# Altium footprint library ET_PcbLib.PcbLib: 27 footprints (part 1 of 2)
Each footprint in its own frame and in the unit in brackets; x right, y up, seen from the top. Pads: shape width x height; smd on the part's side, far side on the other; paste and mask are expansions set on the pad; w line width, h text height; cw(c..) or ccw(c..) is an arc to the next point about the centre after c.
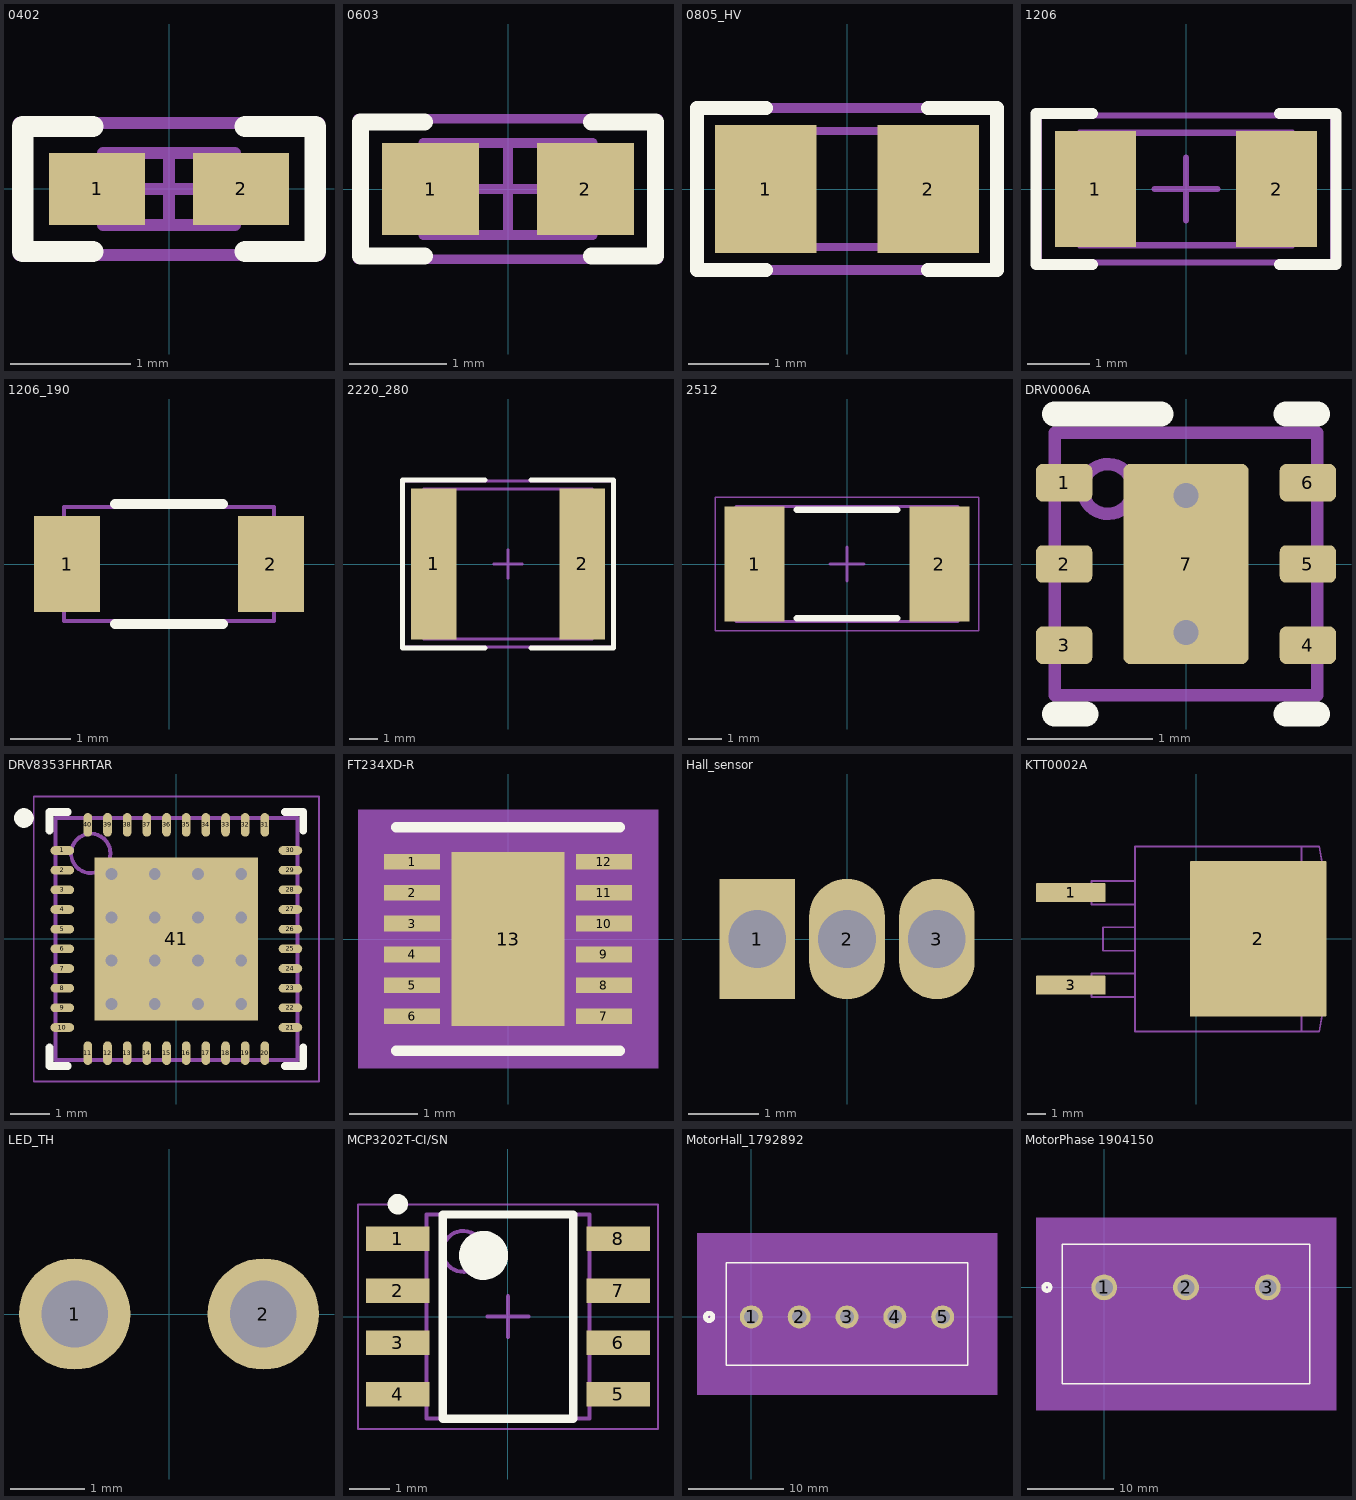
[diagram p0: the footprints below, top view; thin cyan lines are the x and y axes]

## 0402 [mm] "0402 from SM-752 data"
height 0.6
pads (2):
  rect 0.8x0.6 smd: 1(-0.6,0) 2(0.6,0)
Top Overlay:
  lines w0.178: -0.635,-0.521 -1.219,-0.521 -1.219,0.521 -0.635,0.521 ; 0.635,-0.521 1.219,-0.521 1.219,0.521 0.635,0.521
Mechanical 5:
  lines w0.1: -1.25,-0.55 1.25,-0.55 1.25,0.55 -1.25,0.55 -1.25,-0.55
  text ".Designator" at -1.117,-0.305 h0.61
Mechanical 13:
  lines w0.1: -0.35,-0.3 -0.35,0.3 ; 0.35,-0.3 0.35,0.3 ; -0.55,-0.3 -0.55,0.3 0.55,0.3 0.55,-0.3 -0.55,-0.3
Mechanical 15:
  lines w0.1: -0.3,0 0.3,0 ; 0,-0.3 0,0.3 ; -1.25,-0.55 -1.25,0.55 1.25,0.55 1.25,-0.55 -1.25,-0.55
3D body: height 0.6, standoff 0, extent -0.549,-0.299 -0.351,0.299
3D body: height 0.6, standoff 0, extent -0.349,-0.299 0.349,0.299
3D body: height 0.6, standoff 0, extent 0.351,-0.299 0.549,0.299

## 0603 [mm] "0603 from SM-752 data"
height 1
pads (2):
  rect 1x0.95 smd: 1(-0.8,0) 2(0.8,0)
Top Overlay:
  lines w0.178: -0.864,-0.691 -1.524,-0.691 -1.524,0.693 -0.864,0.693 ; 0.864,-0.691 1.524,-0.691 1.524,0.693 0.864,0.693
Mechanical 5:
  lines w0.1: -1.55,-0.725 -1.55,0.725 1.55,0.725 1.55,-0.725 -1.55,-0.725
  text ".Designator" at -1.397,-0.381 h0.76
Mechanical 13:
  lines w0.1: -0.55,-0.475 -0.55,0.475 ; 0.55,-0.475 0.55,0.475 ; -0.875,-0.475 0.875,-0.475 0.875,0.475 -0.875,0.475 -0.875,-0.475
Mechanical 15:
  lines w0.1: -0.475,0 0.475,0 ; 0,-0.475 0,0.475 ; -1.55,-0.725 1.55,-0.725 1.55,0.725 -1.55,0.725 -1.55,-0.725
3D body: height 1, standoff 0, extent -0.874,-0.474 -0.551,0.474
3D body: height 1, standoff 0, extent -0.549,-0.474 0.549,0.474
3D body: height 1, standoff 0, extent 0.551,-0.474 0.874,0.474

## 0805_HV [mil] "0805 with 30mil clearance between pads"
height 57.09
pads (2):
  rect 50x63 smd: 1(-40,0) 2(40,0)
Top Overlay:
  lines w7: -40,-40 -74,-40 -74,0 -74,40 -40,40 ; 40,-40 74,-40 74,0 74,40 40,40
Mechanical 5:
  lines w5: -74,-40 -74,40 74,40 74,-40 -74,-40
  text ".Designator" at -64,-17 h35
Mechanical 13:
  lines w3.94: -25.59,-28.54 -25.59,28.54 ; 25.59,-28.54 25.59,28.54 ; -43.31,-28.54 -43.31,28.54 43.31,28.54 43.31,-28.54 -43.31,-28.54
3D body: height 57.09, standoff 0, extent 25.61,-28.52 43.29,28.52
3D body: height 57.09, standoff 0, extent -25.57,-28.52 25.57,28.52
3D body: height 57.09, standoff 0, extent -43.29,-28.52 -25.61,28.52

## 1206 [mm] "1206 from SM-752 data"
height 1.35
pads (2):
  rect 1.3x1.85 smd: 1(-1.45,0) 2(1.45,0)
Top Overlay:
  lines w0.178: -1.5,-1.21 -2.4,-1.21 -2.4,1.21 -1.5,1.21 ; 1.5,-1.21 2.4,-1.21 2.4,1.21 1.5,1.21
Mechanical 5:
  lines w0.1: -1.7,-0.9 -1.7,0.9 1.7,0.9 1.7,-0.9 -1.7,-0.9
  text ".Designator" at -1.475,-0.4 h0.81
Mechanical 13:
  lines w0.1: -1.2,-0.9 -1.2,0.9 ; 1.2,-0.9 1.2,0.9 ; -1.7,-0.9 -1.7,0.9 1.7,0.9 1.7,-0.9 -1.7,-0.9
Mechanical 15:
  lines w0.1: -0.5,0 0.5,0 ; 0,-0.5 0,0.5 ; -2.35,-1.175 -2.35,1.175 2.35,1.175 2.35,-1.175 -2.35,-1.175
3D body: height 1.35, standoff 0, extent 1.201,-0.899 1.699,0.899
3D body: height 1.35, standoff 0, extent -1.199,-0.899 1.199,0.899
3D body: height 1.35, standoff 0, extent -1.699,-0.899 -1.201,0.899

## 1206_190 [mm] "1206_190"
height 1.9
pads (2):
  rect 1.1x1.6 smd: 1(-1.7,0) 2(1.7,0)
Top Overlay:
  lines w0.17: -0.9,-1 0.9,-1 ; -0.9,1 0.9,1
Mechanical 5:
  lines w0.07: -1.75,-0.95 -1.75,0.95 1.75,0.95 1.75,-0.95 -1.75,-0.95
  text ".Designator" at -1.5,-0.4 h0.64
3D body: height 1.9, standoff 0, extent 1.301,-0.949 1.749,0.949
3D body: height 1.9, standoff 0, extent -1.299,-0.949 1.299,0.949
3D body: height 1.9, standoff 0, extent -1.749,-0.949 -1.301,0.949

## 2220_280 [mm] "Chip Capacitor, Body 5.7x5.0mm, IPC Medium Density"
height 2.8
pads (2):
  rect 1.6x5.3 smd: 1(-2.6,0) 2(2.6,0)
Top Overlay:
  lines w0.178: -0.811,-2.939 -3.693,-2.939 -3.693,2.939 -0.811,2.939 ; 0.811,-2.939 3.693,-2.939 3.693,2.939 0.811,2.939
Mechanical 5:
  lines w0.1: -2.95,-2.625 2.95,-2.625 2.95,2.625 -2.95,2.625 -2.95,-2.625
  text ".Designator" at -1.875,-0.5 h1.02
Mechanical 13:
  lines w0.1: -2.75,-2.625 -2.75,2.625 ; 2.75,-2.625 2.75,2.625 ; -2.95,-2.625 -2.95,2.625 2.95,2.625 2.95,-2.625 -2.95,-2.625
Mechanical 15:
  lines w0.1: -0.5,0 0.5,0 ; 0,-0.5 0,0.5 ; -3.65,-2.9 -3.65,2.9 3.65,2.9 3.65,-2.9 -3.65,-2.9
3D body: height 2.8, standoff 0, extent -2.949,-2.624 -2.751,2.624
3D body: height 2.8, standoff 0, extent -2.749,-2.624 2.749,2.624
3D body: height 2.8, standoff 0, extent 2.751,-2.624 2.949,2.624

## 2512 [mm] "Chip Resistor, 2-Leads, Body 6.40x3.20mm, IPC Medium Density"
height 0.9
pads (2):
  rect 1.8x3.45 smd: 1(-2.775,0) 2(2.775,0)
Top Overlay:
  lines w0.2: -1.5,-1.625 1.5,-1.625 ; -1.5,1.625 1.5,1.625
Mechanical 13:
  lines w0.1: -3.325,-1.725 -3.325,1.725 3.325,1.725 3.325,-1.725 -3.325,-1.725
Mechanical 15:
  lines w0.05: -3.95,-2 -3.95,2 3.95,2 3.95,-2 -3.95,-2
  lines w0.1: -0.5,0 0.5,0 ; 0,-0.5 0,0.5
3D body "2512.step": height 0.9, standoff 0, extent -3.325,-1.725 3.325,1.725

## DRV0006A [mm] "SON, 6-Leads, Body 2x2mm, Pitch 0.65mm, Thermal Pad 1.6x1mm, TI Recommended"
height 0.8
pads (7):
  rrect33% 0.45x0.3 smd: 1(-0.975,0.65) 2(-0.975,0) 3(-0.975,-0.65) 4(0.975,-0.65) 5(0.975,0) 6(0.975,0.65)
  rrect10% 1x1.6 smd paste-0.5: 7(0,0)
via 0,0.55 diameter 0.5 hole 0.2
via 0,-0.55 diameter 0.5 hole 0.2
Top Overlay:
  lines w0.2: -1.05,-1.2 -0.8,-1.2 ; -1.05,1.2 -0.2,1.2 ; 0.8,-1.2 1.05,-1.2 ; 0.8,1.2 1.05,1.2
Top Paste:
  region: 0.475,-0.733 0.475,0.733 -0.474,0.733 -0.474,-0.733
Mechanical 5:
  circle w0.1: c-0.625,0.6 r0.2
  lines w0.1: -1.05,-1.05 -1.05,1.05 1.05,1.05 1.05,-1.05 -1.05,-1.05
  text ".Designator" at -0.9,-0.5 h0.51
3D body: height 0.8, standoff 0, extent -1.05,-1.05 1.05,1.05
3D body: height 0.81, standoff 0.5, extent -0.824,0.401 -0.426,0.799

## DRV8353FHRTAR [mm] "QFN, 40-Leads, Body 6.00x6.00mm, Pitch 0.50mm, Thermal Pad 4.15x4.15mm, IPC Medium Density"
height 0.8
pads (41):
  oval 0.6x0.22 smd: 1(-2.9,2.25) 2(-2.9,1.75) 3(-2.9,1.25) 4(-2.9,0.75) 5(-2.9,0.25) 6(-2.9,-0.25) 7(-2.9,-0.75) 8(-2.9,-1.25) 9(-2.9,-1.75) 10(-2.9,-2.25) 21(2.9,-2.25) 22(2.9,-1.75) 23(2.9,-1.25) 24(2.9,-0.75) 25(2.9,-0.25) 26(2.9,0.25) 27(2.9,0.75) 28(2.9,1.25) 29(2.9,1.75) 30(2.9,2.25)
  oval 0.22x0.6 smd: 11(-2.25,-2.9) 12(-1.75,-2.9) 13(-1.25,-2.9) 14(-0.75,-2.9) 15(-0.25,-2.9) 16(0.25,-2.9) 17(0.75,-2.9) 18(1.25,-2.9) 19(1.75,-2.9) 20(2.25,-2.9) 31(2.25,2.9) 32(1.75,2.9) 33(1.25,2.9) 34(0.75,2.9) 35(0.25,2.9) 36(-0.25,2.9) 37(-0.75,2.9) 38(-1.25,2.9) 39(-1.75,2.9) 40(-2.25,2.9)
  rect 4.15x4.15 smd: 41(0,0)
via 1.65,-1.65 diameter 0.6 hole 0.3
via 0.55,-1.65 diameter 0.6 hole 0.3
via -0.55,-1.65 diameter 0.6 hole 0.3
via -1.65,-1.65 diameter 0.6 hole 0.3
via 1.65,-0.55 diameter 0.6 hole 0.3
via 0.55,-0.55 diameter 0.6 hole 0.3
via -0.55,-0.55 diameter 0.6 hole 0.3
via -1.65,-0.55 diameter 0.6 hole 0.3
via 1.65,0.55 diameter 0.6 hole 0.3
via 0.55,0.55 diameter 0.6 hole 0.3
via -0.55,0.55 diameter 0.6 hole 0.3
via -1.65,0.55 diameter 0.6 hole 0.3
via 1.65,1.65 diameter 0.6 hole 0.3
via 0.55,1.65 diameter 0.6 hole 0.3
via -0.55,1.65 diameter 0.6 hole 0.3
via -1.65,1.65 diameter 0.6 hole 0.3
Top Overlay:
  circle w0.25: c-3.875,3.075 r0.125
  lines w0.2: -3.225,-2.76 -3.225,-3.225 -2.76,-3.225 ; -3.225,2.76 -3.225,3.225 -2.76,3.225 ; 2.76,-3.225 3.225,-3.225 3.225,-2.76 ; 2.76,3.225 3.225,3.225 3.225,2.76
Mechanical 13:
  circle w0.1: c-2.175,2.175 r0.5
  lines w0.1: -3.075,-3.075 3.075,-3.075 3.075,3.075 -3.075,3.075 -3.075,-3.075
Mechanical 15:
  lines w0.05: -3.625,-3.625 3.625,-3.625 3.625,3.625 -3.625,3.625 -3.625,-3.625
  lines w0.1: -0.5,0 0.5,0 ; 0,-0.5 0,0.5
3D body "QFN50P600X600X80_HS-41N.step": height 0.8, standoff 0, extent -3.076,-3.076 3.076,3.076

## FT234XD-R [mil]
pads (13):
  rect 32x9 smd paste+0 mask+0: 1(-55,44.29) 2(-55,26.57) 3(-55,8.86) 4(-55,-8.86) 5(-55,-26.57) 6(-55,-44.29) 7(55,-44.29) 8(55,-26.57) 9(55,-8.86) 10(55,8.86) 11(55,26.57) 12(55,44.29)
  rect 65x100 smd paste+0 mask+0: 13(0,0)
Top Overlay:
  lines w6: -64,-64 64,-64 ; -64,64 64,64
Top Paste:
  region: 28.56,-3.94 -28.56,-3.94 -28.56,-46.06 28.56,-46.06
  region: 28.56,46.06 -28.56,46.06 -28.56,3.94 28.56,3.94
Mechanical 5:
  region: 86,-74 -86,-74 -86,74 86,74
Mechanical 13:
  lines w0: -12,59 ccw(c0,59) 12,59
  lines w1: -59,-59 -59,59 59,59 59,-59 -59,-59
Mechanical 15:
  region: -69,-58.79 -81,-58.79 -81,58.79 -69,58.79 -69,69 69,69 69,58.79 81,58.79 81,-58.79 69,-58.79 69,-69 -69,-69
  lines w6: -81,-58.79 -69,-58.79 -69,-69 69,-69 69,-58.79 81,-58.79 81,58.79 69,58.79 69,69 -69,69 -69,58.79 -81,58.79 -81,-58.79
3D body "DFN-12_FTD.step": height 32.09, standoff 0, extent -59.02,-59.02 59.02,59.02

## Hall_sensor [mm]
pads (3):
  rect 1.07x1.7 hole 0.813 mask+0: 1(-1.27,0)
  oval 1.07x1.7 hole 0.813 mask+0: 2(0,0) 3(1.27,0)

## KTT0002A [mm] "TO-263-2"
height 4.7
pads (3):
  rrect10% 3.82x1.05 smd: 1(-6.9,2.54) 3(-6.9,-2.54)
  rrect1% 7.48x8.55 smd paste-4.2: 2(3.4,0)
Top Paste:
  drawing of 42 lines, arcs and shapes, not listed
Mechanical 5:
  lines w0.1: 5.776,-5.088 5.371,-5.088 -3.195,-5.088 -3.374,-5.088 -3.374,5.072 -3.195,5.072 5.371,5.072 5.776,5.072 ; 5.776,-5.088 5.776,-3.183 ; 5.776,-5.088 6.755,-5.088 7.046,-3.437 7.046,3.421 6.755,5.072 5.776,5.072 ; 5.776,-5.088 5.776,-3.183 ; 5.776,-3.183 5.776,3.167 ; 5.776,3.167 5.776,5.072 ; 5.776,3.167 5.776,5.072 ; -8.025,-2.965 -8.025,-2.13 -6.231,-2.13 -5.99,-2.13 -5.757,-2.13 -5.757,-1.9 -5.42,-1.9 -4.783,-1.9 -3.374,-1.9 -3.374,-3.195 -4.783,-3.195 -5.42,-3.195 -5.757,-3.195 -5.757,-2.965 -5.99,-2.965 -6.231,-2.965 -8.025,-2.965 ; -8.025,2.115 -8.025,2.95 -6.231,2.95 -5.99,2.95 -5.757,2.95 -5.757,3.18 -5.42,3.18 -4.783,3.18 -3.374,3.18 -3.374,1.885 -4.783,1.885 -5.42,1.885 -5.757,1.885 -5.757,2.115 -5.99,2.115 -6.231,2.115 -8.025,2.115 ; -5.124,-0.655 -3.374,-0.655 -3.374,0.64 -5.124,0.64 -5.124,-0.655 ; 3.276,-1.008 ccw(c3.276,-0.008) 3.276,0.992 ccw(c3.276,-0.008) 3.276,-1.008
  text ".Designator" at -0.514,1.8 h1.02
3D body "KTT0002A.stp": height 4.67, standoff 0, extent -8.026,-5.08 7.045,5.08

## LED_TH [mm]
pads (2):
  round 1.5 hole 0.9 mask+0: 1(-1.27,0) 2(1.27,0)

## MCP3202T-CI/SN [mm] "SOIC, 8-Leads, Body 4.90x3.90mm, Pitch 1.27mm, IPC Medium Density"
height 1.75
pads (8):
  rect 1.55x0.6 smd: 1(-2.7,1.905) 2(-2.7,0.635) 3(-2.7,-0.635) 4(-2.7,-1.905) 5(2.7,-1.905) 6(2.7,-0.635) 7(2.7,0.635) 8(2.7,1.905)
Top Overlay:
  circle w0.25: c-2.7,2.755 r0.125
  circle w0.6: c-0.6,1.5 r0.3
  lines w0.2: -1.6,-2.5 -1.6,2.5 1.6,2.5 1.6,-2.5 -1.6,-2.5
Mechanical 13:
  circle w0.1: c-1.1,1.6 r0.5
  lines w0.1: -2,-2.5 -2,2.5 2,2.5 2,-2.5 -2,-2.5
Mechanical 15:
  lines w0.05: -3.675,-2.75 -3.675,2.75 3.675,2.75 3.675,-2.75 -3.675,-2.75
  lines w0.1: -0.5,0 0.5,0 ; 0,-0.5 0,0.5
3D body: height 1.75, standoff 0.25, extent -2,-2.5 2,2.5

## MotorHall_1792892 [mm]
pads (5):
  round 2.4 hole 1.5 mask+0: 1(0,0) 2(5,0) 3(10,0) 4(15,0) 5(20,0)
Top Overlay:
  circle w0.508: c-4.405,0 r0.381
  lines w0.152: -2.627,-5.077 22.627,-5.077 22.627,5.677 -2.627,5.677 -2.627,-5.077
Bottom Overlay:
  circle w0.508: c-4.405,0 r0.381
Mechanical 5:
  region: -5.675,8.725 25.675,8.725 25.675,-8.125 -5.675,-8.125
Mechanical 13:
  circle w0.508: c0,1.905 r0.381
  lines w0.025: -2.5,-4.95 22.5,-4.95 22.5,5.55 -2.5,5.55 -2.5,-4.95
Mechanical 15:
  region: 22.754,5.804 -2.754,5.804 -2.754,-5.204 22.754,-5.204
  lines w0.152: -2.754,-5.204 -2.754,5.804 22.754,5.804 22.754,-5.204 -2.754,-5.204
3D body: height 0.25, standoff 0, extent 0,0 0.254,0.254

## MotorPhase 1904150 [mm]
pads (3):
  round 3 hole 2 mask+0: 1(0,0) 2(9.52,0) 3(19.04,0)
Top Overlay:
  circle w0.508: c-6.665,0 r0.381
  lines w0.152: -4.887,-11.227 23.927,-11.227 23.927,5.027 -4.887,5.027 -4.887,-11.227
Bottom Overlay:
  circle w0.508: c-6.665,0 r0.381
Mechanical 5:
  region: -7.935,8.075 26.975,8.075 26.975,-14.275 -7.935,-14.275
Mechanical 13:
  circle w0.508: c0,1.905 r0.381
  lines w0.025: -4.76,-11.1 23.8,-11.1 23.8,4.9 -4.76,4.9 -4.76,-11.1
Mechanical 15:
  region: 24.054,5.154 -5.014,5.154 -5.014,-11.354 24.054,-11.354
  lines w0.152: -5.014,-11.354 -5.014,5.154 24.054,5.154 24.054,-11.354 -5.014,-11.354
3D body: height 0.25, standoff 0, extent 0,0 0.254,0.254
